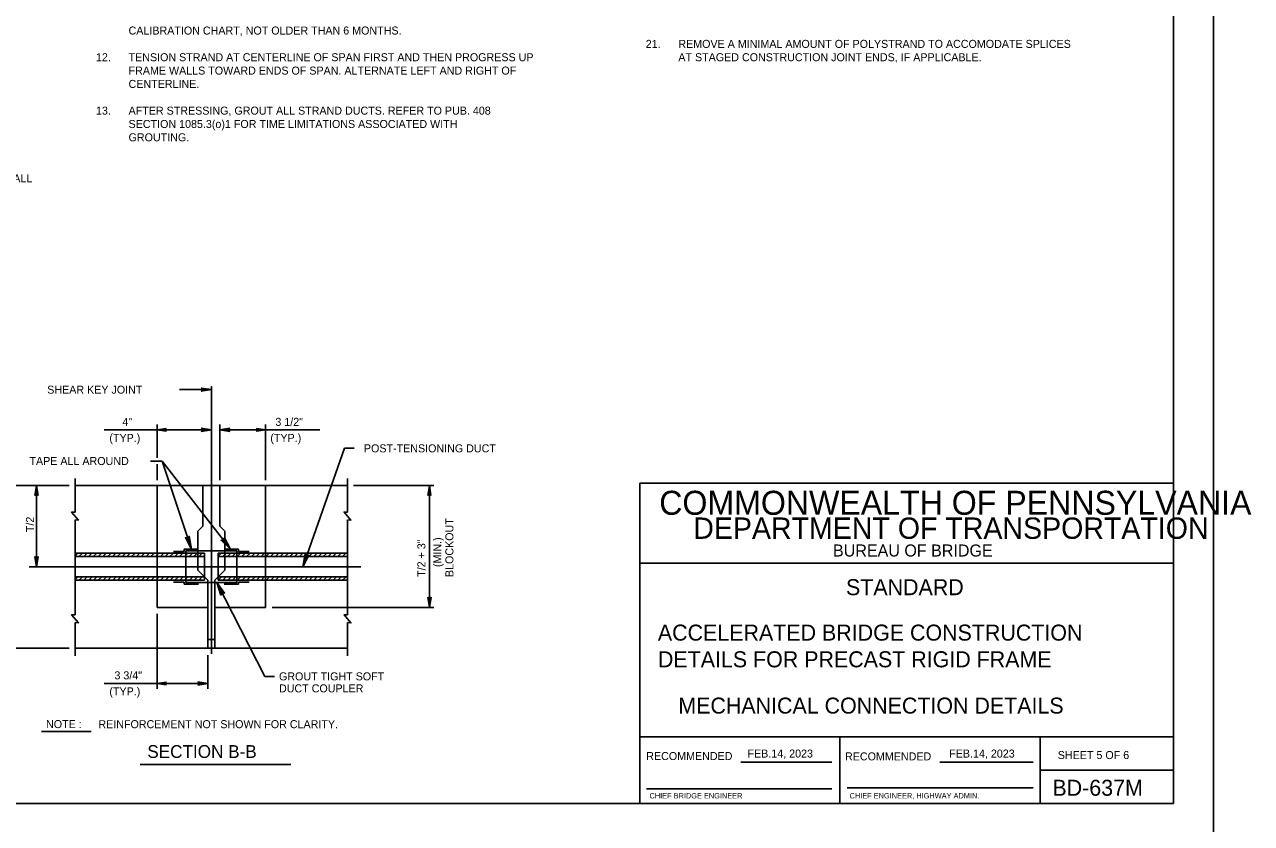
# Model space of a CAD drawing. Extents: x 641328 to 643024, y 298283 to 300065.
# Drawn here: x 642563.8 to 643023.7, y 298884.8 to 299184.1 of the extents above; entities that cross this region are included whole.
import ezdxf

# ---------------------------------------------------------------- set-up
doc = ezdxf.new("R2010")
doc.units = 0
for name, color, linetype in [('2', 7, 'Continuous'), ('DATES', 7, 'Continuous'), ('Default', 7, 'Continuous'), ('PLT-BNDY', 7, 'Continuous'), ('S-TEXT-DIMS-N', 7, 'Continuous'), ('SIGNATORY TITLES', 7, 'Continuous')]:
    doc.layers.add(name, color=color, linetype=linetype)

msp = doc.modelspace()

# ---------------------------------------------------------------- linework, layer by layer
at = {"layer": '2'}
for p, q in [((642994.5, 299456.3), (642994.5, 298892.3)), ((642630.25, 299047.74), (642630.05, 299047.9)), ((642630.05, 299047.9), (642633.86, 299047.31)), ((642630.25, 299047.74), (642630.38, 299047.48)), ((642633.86, 299047.31), (642630.25, 299047.74)), ((642633.86, 299048.48), (642633.86, 298948.36)), ((642621.88, 299047.31), (642633.86, 299047.31)), ((642633.86, 299047.31), (642630.06, 299046.68)), ((642630.06, 299046.68), (642630.26, 299046.86)), ((642630.26, 299046.86), (642633.86, 299047.31)), ((642630.38, 299047.12), (642630.26, 299046.86)), ((642630.38, 299047.48), (642633.86, 299047.31)), ((642630.38, 299047.48), (642630.38, 299047.12)), ((642633.86, 299047.31), (642630.38, 299047.12)), ((642633.86, 299047.31), (642630.38, 299047.3)), ((642613.54, 299021.73), (642613.54, 299034.25)), ((642637.03, 299013.36), (642637.03, 299034.25)), ((642654.18, 299013.36), (642654.18, 299034.25)), ((642633.86, 299032.25), (642593.65, 299032.25)), ((642630.05, 299031.66), (642633.86, 299032.25)), ((642630.25, 299031.82), (642630.05, 299031.66)), ((642633.86, 299032.25), (642630.06, 299032.88)), ((642630.06, 299032.88), (642630.26, 299032.71)), ((642633.86, 299032.25), (642630.25, 299031.82)), ((642630.25, 299031.82), (642630.38, 299032.08)), ((642630.38, 299032.44), (642630.26, 299032.71)), ((642630.26, 299032.71), (642633.86, 299032.25)), ((642633.86, 299032.25), (642630.38, 299032.44)), ((642630.38, 299032.08), (642630.38, 299032.44)), ((642633.86, 299032.25), (642630.38, 299032.26)), ((642630.38, 299032.08), (642633.86, 299032.25)), ((642637.03, 299032.26), (642640.82, 299032.9)), ((642640.63, 299032.72), (642637.03, 299032.26)), ((642637.03, 299032.26), (642640.5, 299032.46)), ((642637.03, 299032.26), (642640.5, 299032.28)), ((642640.5, 299032.1), (642637.03, 299032.26)), ((642637.03, 299032.26), (642640.64, 299031.83)), ((642640.83, 299031.67), (642637.03, 299032.26)), ((642637.03, 299032.25), (642674.51, 299032.25)), ((642640.5, 299032.46), (642640.63, 299032.72)), ((642640.5, 299032.1), (642640.5, 299032.46)), ((642640.64, 299031.83), (642640.5, 299032.1)), ((642640.82, 299032.9), (642640.63, 299032.72)), ((642640.64, 299031.83), (642640.83, 299031.67)), ((642683.82, 299025.38), (642668.1, 298980.96)), ((642615.47, 299020.51), (642626.37, 298987.52)), ((642615.47, 299020.51), (642641.1, 298987.52)), ((642613.54, 299013.36), (642613.54, 299019.36)), ((642580.56, 299011.44), (642550.5, 299011.44)), ((642567.72, 299007.64), (642568.32, 299011.44)), ((642568.32, 299011.44), (642567.88, 299007.83)), ((642568.15, 299007.97), (642568.32, 299011.44)), ((642568.32, 298980.96), (642568.32, 299011.44)), ((642568.32, 299011.44), (642568.51, 299007.97)), ((642568.77, 299007.84), (642568.32, 299011.44)), ((642568.32, 299011.44), (642568.95, 299007.65)), ((642568.32, 299011.44), (642568.33, 299007.97)), ((642582.77, 299001.46), (642582.77, 299014.05)), ((642582.77, 299011.44), (642630.68, 299011.44)), ((642613.54, 298986.04), (642613.54, 299011.44)), ((642630.68, 299011.44), (642630.68, 298996.2)), ((642630.68, 299011.44), (642637.03, 299011.44)), ((642637.03, 299011.44), (642684.94, 299011.44)), ((642637.03, 299011.44), (642637.03, 298996.2)), ((642654.18, 298986.04), (642654.18, 299011.44)), ((642684.94, 299001.46), (642684.94, 299014.05)), ((642687.15, 299011.44), (642717.21, 299011.44)), ((642715.59, 299011.44), (642714.95, 299007.65)), ((642715.13, 299007.84), (642715.59, 299011.44)), ((642715.59, 299011.44), (642715.39, 299007.97)), ((642715.59, 299011.44), (642715.57, 299007.97)), ((642715.59, 298965.72), (642715.59, 299011.44)), ((642715.75, 299007.97), (642715.59, 299011.44)), ((642715.59, 299011.44), (642716.02, 299007.83)), ((642716.18, 299007.64), (642715.59, 299011.44)), ((642994.5, 299012.3), (642794.5, 299012.3)), ((642794.5, 299012.3), (642794.5, 298892.3)), ((642994.5, 298892.3), (642994.5, 299012.3)), ((642567.88, 299007.83), (642567.72, 299007.64)), ((642567.88, 299007.83), (642568.15, 299007.97)), ((642568.15, 299007.97), (642568.51, 299007.97)), ((642568.51, 299007.97), (642568.77, 299007.84)), ((642568.95, 299007.65), (642568.77, 299007.84)), ((642714.95, 299007.65), (642715.13, 299007.84)), ((642715.39, 299007.97), (642715.13, 299007.84)), ((642715.75, 299007.97), (642715.39, 299007.97)), ((642716.02, 299007.83), (642715.75, 299007.97)), ((642716.02, 299007.83), (642716.18, 299007.64)), ((642582.77, 298962.94), (642582.77, 298998.57)), ((642684.94, 298962.94), (642684.94, 298998.57)), ((642630.68, 298996.2), (642628.78, 298994.3)), ((642628.78, 298994.3), (642628.78, 298987.52)), ((642637.03, 298996.2), (642638.94, 298994.3)), ((642638.94, 298994.3), (642638.94, 298987.52)), ((642568.32, 298980.96), (642567.68, 298984.76)), ((642567.68, 298984.76), (642567.86, 298984.56)), ((642568.12, 298984.43), (642567.86, 298984.56)), ((642567.86, 298984.56), (642568.32, 298980.96)), ((642568.48, 298984.44), (642568.12, 298984.43)), ((642568.32, 298980.96), (642568.12, 298984.43)), ((642568.32, 298980.96), (642568.3, 298984.43)), ((642568.91, 298984.76), (642568.32, 298980.96)), ((642568.32, 298980.96), (642568.75, 298984.57)), ((642568.48, 298984.44), (642568.32, 298980.96)), ((642568.75, 298984.57), (642568.48, 298984.44)), ((642568.75, 298984.57), (642568.91, 298984.76)), ((642582.77, 298986.04), (642631.32, 298986.04)), ((642582.77, 298985.09), (642583.72, 298986.04)), ((642582.77, 298984.77), (642631.32, 298984.77)), ((642584.23, 298984.77), (642585.5, 298986.04)), ((642586.03, 298984.77), (642587.3, 298986.04)), ((642587.82, 298984.77), (642589.09, 298986.04)), ((642589.62, 298984.77), (642590.89, 298986.04)), ((642591.41, 298984.77), (642592.68, 298986.04)), ((642593.21, 298984.77), (642594.48, 298986.04)), ((642595, 298984.77), (642596.27, 298986.04)), ((642596.8, 298984.77), (642598.07, 298986.04)), ((642598.6, 298984.77), (642599.87, 298986.04)), ((642600.39, 298984.77), (642601.66, 298986.04)), ((642602.19, 298984.77), (642603.46, 298986.04)), ((642603.98, 298984.77), (642605.25, 298986.04)), ((642605.78, 298984.77), (642607.05, 298986.04)), ((642607.58, 298984.77), (642608.85, 298986.04)), ((642609.37, 298984.77), (642610.64, 298986.04)), ((642611.17, 298984.77), (642612.44, 298986.04)), ((642612.96, 298984.77), (642614.23, 298986.04)), ((642613.54, 298975.88), (642613.54, 298986.04)), ((642614.76, 298984.77), (642616.03, 298986.04)), ((642616.56, 298984.77), (642617.83, 298986.04)), ((642618.35, 298984.77), (642619.62, 298986.04)), ((642619.66, 298986.68), (642623.7, 298986.68)), ((642620.15, 298984.77), (642621.42, 298986.04)), ((642621.94, 298984.77), (642623.21, 298986.04)), ((642623.7, 298986.68), (642623.7, 298987.52)), ((642623.7, 298987.52), (642629.05, 298987.52)), ((642623.74, 298984.77), (642625.01, 298986.04)), ((642624.33, 298986.04), (642624.33, 298986.89)), ((642624.33, 298986.89), (642643.38, 298986.89)), ((642624.33, 298986.04), (642624.33, 298975.88)), ((642625.54, 298984.77), (642626.81, 298986.04)), ((642627.33, 298984.77), (642628.6, 298986.04)), ((642628.78, 298987.52), (642628.78, 298979.69)), ((642629.13, 298984.77), (642630.4, 298986.04)), ((642630.92, 298984.77), (642631.32, 298985.16)), ((642631.32, 298986.04), (642631.32, 298975.88)), ((642631.32, 298975.88), (642631.32, 298986.04)), ((642636.31, 298984.77), (642637.58, 298986.04)), ((642636.4, 298986.04), (642636.4, 298975.88)), ((642636.4, 298986.04), (642684.94, 298986.04)), ((642636.4, 298984.77), (642684.94, 298984.77)), ((642638.11, 298984.77), (642639.38, 298986.04)), ((642644.02, 298987.52), (642638.66, 298987.52)), ((642638.94, 298987.52), (642638.94, 298979.69)), ((642639.91, 298984.77), (642641.18, 298986.04)), ((642641.7, 298984.77), (642642.97, 298986.04)), ((642643.38, 298986.89), (642643.38, 298986.04)), ((642643.38, 298986.04), (642643.38, 298975.04)), ((642643.5, 298984.77), (642644.77, 298986.04)), ((642644.02, 298986.68), (642644.02, 298987.52)), ((642648.05, 298986.68), (642644.02, 298986.68)), ((642645.29, 298984.77), (642646.56, 298986.04)), ((642647.09, 298984.77), (642648.36, 298986.04)), ((642648.89, 298984.77), (642650.16, 298986.04)), ((642650.68, 298984.77), (642651.95, 298986.04)), ((642652.48, 298984.77), (642653.75, 298986.04)), ((642654.18, 298975.88), (642654.18, 298986.04)), ((642654.27, 298984.77), (642655.54, 298986.04)), ((642656.07, 298984.77), (642657.34, 298986.04)), ((642657.87, 298984.77), (642659.14, 298986.04)), ((642659.66, 298984.77), (642660.93, 298986.04)), ((642661.46, 298984.77), (642662.73, 298986.04)), ((642663.25, 298984.77), (642664.52, 298986.04)), ((642665.05, 298984.77), (642666.32, 298986.04)), ((642666.85, 298984.77), (642668.12, 298986.04)), ((642668.64, 298984.77), (642669.91, 298986.04)), ((642670.44, 298984.77), (642671.71, 298986.04)), ((642672.23, 298984.77), (642673.5, 298986.04)), ((642674.03, 298984.77), (642675.3, 298986.04)), ((642675.83, 298984.77), (642677.1, 298986.04)), ((642677.62, 298984.77), (642678.89, 298986.04)), ((642679.42, 298984.77), (642680.69, 298986.04)), ((642681.21, 298984.77), (642682.48, 298986.04)), ((642683.01, 298984.77), (642684.28, 298986.04)), ((642565.56, 298980.96), (642570.9, 298980.96)), ((642632.59, 298975.88), (642628.78, 298979.69)), ((642635.13, 298975.88), (642638.94, 298979.69)), ((642994.5, 298982.3), (642794.5, 298982.3)), ((642582.77, 298977.15), (642631.32, 298977.15)), ((642582.77, 298976.13), (642583.79, 298977.15)), ((642582.77, 298975.88), (642631.32, 298975.88)), ((642584.31, 298975.88), (642585.58, 298977.15)), ((642586.1, 298975.88), (642587.37, 298977.15)), ((642586.63, 298975.88), (642631.32, 298975.88)), ((642587.9, 298975.88), (642589.17, 298977.15)), ((642589.69, 298975.88), (642590.96, 298977.15)), ((642591.49, 298975.88), (642592.76, 298977.15)), ((642593.28, 298975.88), (642594.55, 298977.15)), ((642595.08, 298975.88), (642596.35, 298977.15)), ((642596.87, 298975.88), (642598.14, 298977.15)), ((642598.67, 298975.88), (642599.94, 298977.15)), ((642600.47, 298975.88), (642601.74, 298977.15)), ((642602.26, 298975.88), (642603.53, 298977.15)), ((642604.06, 298975.88), (642605.33, 298977.15)), ((642605.85, 298975.88), (642607.12, 298977.15)), ((642607.65, 298975.88), (642608.92, 298977.15)), ((642609.45, 298975.88), (642610.72, 298977.15)), ((642611.24, 298975.88), (642612.51, 298977.15)), ((642613.04, 298975.88), (642614.31, 298977.15)), ((642613.54, 298965.72), (642613.54, 298975.88)), ((642614.83, 298975.88), (642616.1, 298977.15)), ((642616.63, 298975.88), (642617.9, 298977.15)), ((642618.43, 298975.88), (642619.7, 298977.15)), ((642619.66, 298975.25), (642623.7, 298975.25)), ((642620.22, 298975.88), (642621.49, 298977.15)), ((642622.02, 298975.88), (642623.29, 298977.15)), ((642622.16, 298975.88), (642622.16, 298975.88)), ((642623.17, 298975.83), (642623.2, 298975.78)), ((642623.7, 298975.25), (642623.7, 298974.4)), ((642623.7, 298974.4), (642629.05, 298974.4)), ((642623.81, 298975.88), (642625.08, 298977.15)), ((642624.33, 298975.04), (642624.33, 298975.88)), ((642643.38, 298975.04), (642624.33, 298975.04)), ((642625.61, 298975.88), (642626.88, 298977.15)), ((642627.41, 298975.88), (642628.68, 298977.15)), ((642629.2, 298975.88), (642630.47, 298977.15)), ((642631, 298975.88), (642631.32, 298976.2)), ((642632.59, 298975.88), (642632.59, 298975.04)), ((642632.59, 298975.04), (642632.59, 298950.48)), ((642635.13, 298975.88), (642635.13, 298975.04)), ((642635.13, 298975.04), (642635.13, 298950.48)), ((642653.96, 298939.9), (642635.9, 298975.04)), ((642636.39, 298975.88), (642637.66, 298977.15)), ((642636.4, 298977.15), (642684.94, 298977.15)), ((642636.4, 298975.88), (642684.94, 298975.88)), ((642636.4, 298975.88), (642684.94, 298975.88)), ((642638.18, 298975.88), (642639.45, 298977.15)), ((642644.02, 298974.4), (642638.66, 298974.4)), ((642639.98, 298975.88), (642641.25, 298977.15)), ((642641.77, 298975.88), (642643.04, 298977.15)), ((642643.38, 298975.88), (642643.38, 298975.04)), ((642643.57, 298975.88), (642644.84, 298977.15)), ((642648.05, 298975.25), (642644.02, 298975.25)), ((642644.02, 298975.25), (642644.02, 298974.4)), ((642645.37, 298975.88), (642646.64, 298977.15)), ((642647.16, 298975.88), (642648.43, 298977.15)), ((642648.96, 298975.88), (642650.23, 298977.15)), ((642650.76, 298975.88), (642652.03, 298977.15)), ((642652.55, 298975.88), (642653.82, 298977.15)), ((642654.18, 298965.72), (642654.18, 298975.88)), ((642654.35, 298975.88), (642655.62, 298977.15)), ((642656.14, 298975.88), (642657.41, 298977.15)), ((642657.94, 298975.88), (642659.21, 298977.15)), ((642659.74, 298975.88), (642661.01, 298977.15)), ((642661.53, 298975.88), (642662.8, 298977.15)), ((642663.33, 298975.88), (642664.6, 298977.15)), ((642665.12, 298975.88), (642666.39, 298977.15)), ((642666.92, 298975.88), (642668.19, 298977.15)), ((642668.72, 298975.88), (642669.99, 298977.15)), ((642670.51, 298975.88), (642671.78, 298977.15)), ((642672.31, 298975.88), (642673.58, 298977.15)), ((642674.1, 298975.88), (642675.37, 298977.15)), ((642675.9, 298975.88), (642677.17, 298977.15)), ((642677.7, 298975.88), (642678.97, 298977.15)), ((642679.49, 298975.88), (642680.76, 298977.15)), ((642681.29, 298975.88), (642682.56, 298977.15)), ((642683.08, 298975.88), (642684.35, 298977.15)), ((642613.54, 298965.72), (642632.59, 298965.72)), ((642635.13, 298965.72), (642654.18, 298965.72)), ((642656.6, 298965.72), (642717.21, 298965.72)), ((642715.16, 298969.33), (642715, 298969.52)), ((642715, 298969.52), (642715.59, 298965.72)), ((642715.16, 298969.33), (642715.42, 298969.2)), ((642715.59, 298965.72), (642715.16, 298969.33)), ((642715.42, 298969.2), (642715.59, 298965.72)), ((642715.42, 298969.2), (642715.78, 298969.19)), ((642715.59, 298965.72), (642716.22, 298969.52)), ((642716.04, 298969.32), (642715.59, 298965.72)), ((642715.59, 298965.72), (642715.78, 298969.19)), ((642715.59, 298965.72), (642715.6, 298969.19)), ((642715.78, 298969.19), (642716.04, 298969.32)), ((642716.22, 298969.52), (642716.04, 298969.32)), ((642613.54, 298963.3), (642613.54, 298935.28)), ((642582.77, 298947.58), (642582.77, 298960.05)), ((642684.94, 298947.58), (642684.94, 298960.05)), ((642580.56, 298950.48), (642550.5, 298950.48)), ((642582.77, 298950.48), (642632.59, 298950.48)), ((642632.59, 298947.8), (642632.59, 298935.28)), ((642635.13, 298950.48), (642684.94, 298950.48)), ((642628.98, 298937.71), (642628.78, 298937.87)), ((642628.78, 298937.87), (642632.59, 298937.28)), ((642628.98, 298937.71), (642629.11, 298937.45)), ((642632.59, 298937.28), (642628.98, 298937.71)), ((642629.11, 298937.45), (642632.59, 298937.28)), ((642629.11, 298937.45), (642629.11, 298937.08)), ((642632.59, 298937.28), (642593.65, 298937.28)), ((642632.59, 298937.28), (642628.79, 298936.65)), ((642628.79, 298936.65), (642628.99, 298936.82)), ((642628.99, 298936.82), (642632.59, 298937.28)), ((642629.11, 298937.08), (642628.99, 298936.82)), ((642632.59, 298937.28), (642629.11, 298937.08)), ((642632.59, 298937.28), (642629.11, 298937.26)), ((642570.2, 298919.26), (642588.8, 298919.26)), ((642994.5, 298917.3), (642794.5, 298917.3)), ((642869.5, 298892.3), (642869.5, 298917.3)), ((642944.5, 298917.3), (642944.5, 298892.3)), ((642607.13, 298906.86), (642663.6, 298906.86)), ((642832.35, 298907.8), (642866.39, 298907.8)), ((642906.95, 298907.8), (642941.92, 298907.8)), ((642944.5, 298904.8), (642994.5, 298904.8)), ((642797, 298897.8), (642866.39, 298897.8)), ((642872.13, 298898.17), (642941.92, 298898.17)), ((642994.5, 298892.3), (642208.51, 298892.3)), ((642794.5, 298892.3), (642994.5, 298892.3))]:
    msp.add_line(p, q, dxfattribs=at)
for points in [[(642633.86, 299048.48), (642633.86, 299048.48), (642633.86, 299046.15), (642633.86, 299046.15)], [(642632.59, 298950.48), (642635.13, 298950.48), (642635.13, 298953.73), (642632.59, 298953.73)]]:
    msp.add_lwpolyline(points, close=True, dxfattribs=at)
for points in [[(642616.79, 299032.62), (642616.66, 299032.37), (642613.54, 299032.25), (642616.79, 299032.62), (642616.91, 299032.75), (642613.54, 299032.25), (642616.66, 299032.12), (642616.79, 299031.87), (642613.54, 299032.25), (642616.91, 299031.75), (642616.79, 299031.87)], [(642650.93, 299032.62), (642651.05, 299032.37), (642654.18, 299032.25), (642650.93, 299032.62), (642650.8, 299032.75), (642654.18, 299032.25), (642651.05, 299032.12), (642650.93, 299031.87), (642654.18, 299032.25), (642650.8, 299031.75), (642650.93, 299031.87)], [(642582.85, 298998.57), (642584.01, 298998.45), (642581.46, 299001.42), (642582.77, 299001.46)], [(642685.02, 298998.57), (642686.18, 298998.45), (642683.63, 299001.42), (642684.94, 299001.46)], [(642624.38, 298991.72), (642624.75, 298991.66), (642626.37, 298987.52), (642624.38, 298991.72), (642624.11, 298991.88), (642626.37, 298987.52), (642625.19, 298991.81), (642625.45, 298992.06), (642626.37, 298987.52), (642625.58, 298992.37), (642625.45, 298992.06)], [(642637.81, 298990.81), (642638.18, 298990.88), (642641.1, 298987.52), (642637.81, 298990.81), (642637.51, 298990.87), (642641.1, 298987.52), (642638.55, 298991.16), (642638.71, 298991.49), (642641.1, 298987.52), (642638.74, 298991.83), (642638.71, 298991.49)], [(642670.19, 298985.12), (642669.81, 298985.07), (642668.1, 298980.96), (642670.19, 298985.12), (642670.46, 298985.27), (642668.1, 298980.96), (642669.38, 298985.22), (642669.12, 298985.48), (642668.1, 298980.96), (642668.99, 298985.79), (642669.12, 298985.48)], [(642638.52, 298971.2), (642638.15, 298971.2), (642635.9, 298975.04), (642638.52, 298971.2), (642638.81, 298971.08), (642635.9, 298975.04), (642637.73, 298970.99), (642637.51, 298970.69), (642635.9, 298975.04), (642637.43, 298970.37), (642637.51, 298970.69)], [(642582.85, 298960.04), (642584.01, 298959.92), (642581.46, 298962.89), (642582.77, 298962.94)], [(642685.02, 298960.04), (642686.18, 298959.92), (642683.63, 298962.89), (642684.94, 298962.94)], [(642616.79, 298936.9), (642616.66, 298937.15), (642613.54, 298937.28), (642616.79, 298936.9), (642616.91, 298936.78), (642613.54, 298937.28), (642616.66, 298937.4), (642616.79, 298937.65), (642613.54, 298937.28), (642616.91, 298937.78), (642616.79, 298937.65)]]:
    msp.add_lwpolyline(points, dxfattribs=at)
at = {"layer": 'Default'}
for p, q in [((642687.42, 299025.38), (642683.82, 299025.38)), ((642615.47, 299020.51), (642611.05, 299020.51)), ((642657.56, 298939.9), (642653.96, 298939.9))]:
    msp.add_line(p, q, dxfattribs=at)
at = {"layer": 'PLT-BNDY'}
msp.add_lwpolyline([(642168.51, 299471.3), (643009.51, 299471.3), (643009.51, 298877.3), (642168.51, 298877.3)], close=True, dxfattribs=at)
at = {"layer": 'S-TEXT-DIMS-N'}
msp.add_line((642568.42, 298980.96), (642689.87, 298980.96), dxfattribs=at)

# ---------------------------------------------------------------- texts
at = {"layer": '2'}
for s, height, p in [('CALIBRATION CHART, NOT OLDER THAN 6 MONTHS. ', 3, (642602.83, 299180.34)), ('21.', 3, (642796.69, 299175.34)), ('REMOVE A MINIMAL AMOUNT OF POLYSTRAND TO ACCOMODATE SPLICES ', 3, (642808.91, 299175.34)), ('12.', 3, (642590.61, 299170.34)), ('TENSION STRAND AT CENTERLINE OF SPAN FIRST AND THEN PROGRESS UP ', 3, (642602.83, 299170.34)), ('AT STAGED CONSTRUCTION JOINT ENDS, IF APPLICABLE.', 3, (642808.91, 299170.34)), ('FRAME WALLS TOWARD ENDS OF SPAN. ALTERNATE LEFT AND RIGHT OF ', 3, (642602.83, 299165.34)), ('CENTERLINE.', 3, (642602.83, 299160.34)), ('13.', 3, (642590.61, 299150.34)), ('AFTER STRESSING, GROUT ALL STRAND DUCTS. REFER TO PUB. 408 ', 3, (642602.83, 299150.34)), ('SECTION 1085.3(o)1 FOR TIME LIMITATIONS ASSOCIATED WITH ', 3, (642602.83, 299145.34)), ('GROUTING.', 3, (642602.83, 299140.34)), ('STRAND, DUCT AND WALL', 3, (642515.3, 299124.96)), ('  SHEAR KEY JOINT', 3, (642570.11, 299045.8)), ('4"', 3, (642600.53, 299033.75)), ('3 1/2"', 3, (642657.86, 299033.75)), ('(TYP.)', 3, (642595.64, 299027.75)), ('(TYP.)', 3, (642655.97, 299027.75)), ('  POST-TENSIONING DUCT', 3, (642688.81, 299023.82)), ('TAPE ALL AROUND', 3, (642565.68, 299019.08)), ('COMMONWEALTH OF PENNSYLVANIA', 9, (642801.75, 299000.42)), ('DEPARTMENT OF TRANSPORTATION', 8.0002, (642814.5, 298991.42)), ('BUREAU OF BRIDGE', 4.5, (642866.88, 298984.8)), ('STANDARD', 6, (642871.75, 298970.31)), ('ACCELERATED BRIDGE CONSTRUCTION', 6, (642801.23, 298953.29)), ('DETAILS FOR PRECAST RIGID FRAME', 6, (642801.25, 298943.29)), ('3 3/4"', 3, (642597.53, 298938.78)), ('GROUT TIGHT SOFT', 3, (642659.21, 298938.4)), ('(TYP.)', 3, (642595.64, 298932.78)), ('DUCT COUPLER', 3, (642659.21, 298933.9)), ('MECHANICAL CONNECTION DETAILS', 6, (642808.9, 298925.95)), ('NOTE :', 3, (642571.9, 298920.52)), ('REINFORCEMENT NOT SHOWN FOR CLARITY.', 3, (642591.52, 298920.49)), ('SECTION B-B', 4.8, (642609.85, 298909.34)), ('SHEET 5 OF 6', 3, (642951.14, 298908.92)), ('BD-637M', 6, (642949.13, 298895.17))]:
    msp.add_text(s, height=height, dxfattribs=at).set_placement(p)
for s, rotation, p in [('T/2', 90, (642567.4, 298993.93)), ('BLOCKOUT', 90, (642724.59, 298977.09)), ('T/2 + 3"', 90, (642714.09, 298977.17)), ('(MIN.)', 90, (642720.09, 298980.85)), ('RECOMMENDED', 360, (642796.88, 298908.55)), ('RECOMMENDED', 360, (642871.39, 298908.42))]:
    msp.add_text(s, height=3, rotation=rotation, dxfattribs=at).set_placement(p)
at = {"layer": 'DATES'}
for p in [(642834.84, 298909.48), (642910.46, 298909.48)]:
    msp.add_text('FEB.14, 2023', height=3, dxfattribs=at).set_placement(p)
at = {"layer": 'SIGNATORY TITLES'}
for s, p in [('CHIEF BRIDGE ENGINEER', (642798.1, 298894.17)), ('CHIEF ENGINEER, HIGHWAY ADMIN.', (642873.1, 298894.17))]:
    msp.add_text(s, height=2, dxfattribs=at).set_placement(p)

doc.saveas('drawing.dxf')
